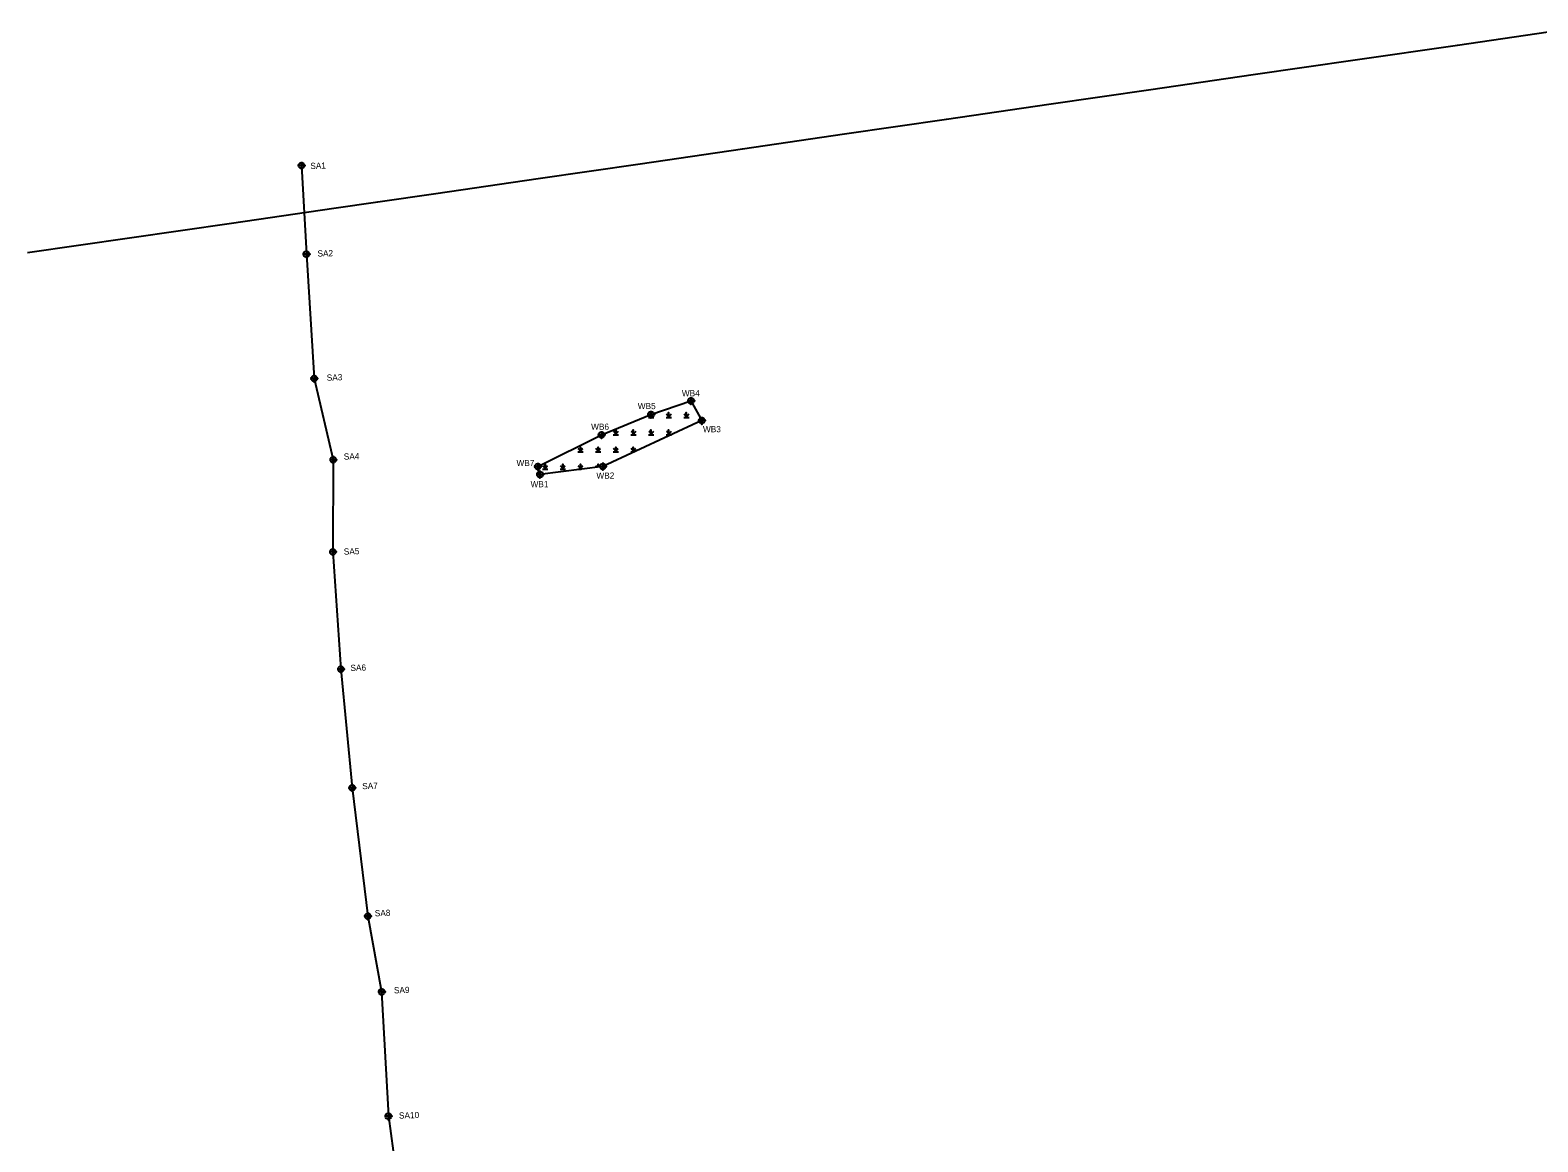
# Model space of a CAD drawing. Extents: x 1616941 to 1621864, y 896903 to 900301.
# Drawn here: x 1619402 to 1620623, y 899343 to 900243 of the extents above; entities that cross this region are included whole.
import ezdxf

# ---------------------------------------------------------------- set-up
doc = ezdxf.new("R2010")
doc.units = 0
for name, color, linetype in [('Default', 7, 'Continuous'), ('Exist Hydro Swamp or Marsh', 7, 'Continuous'), ('Sheet Block Revision CELL', 7, 'Continuous'), ('Sheet Layout Plan Border', 7, 'Continuous'), ('Sheet North Arrow Point CELL', 7, 'Continuous'), ('Sheet Plan CELL', 7, 'Continuous'), ('Sheet Plot Border Outside CELL', 7, 'Continuous'), ('Sheet Sticker Exception Certification CELL', 7, 'Continuous')]:
    doc.layers.add(name, color=color, linetype=linetype)

msp = doc.modelspace()

# ---------------------------------------------------------------- linework, layer by layer
at = {"layer": 'Default'}
msp.add_lwpolyline([(1619400.1, 900062.7), (1619482.8, 900074.7), (1619565.5, 900086.7), (1619648.2, 900098.7), (1619683.8, 900103.9), (1619730.9, 900110.7), (1619813.7, 900122.7), (1619896.4, 900134.7), (1619979.1, 900146.8), (1620061.8, 900158.8), (1620144.5, 900170.8), (1620227.3, 900182.8), (1620310, 900194.8), (1620392.7, 900206.8), (1620475.4, 900218.8), (1620558.1, 900230.8), (1620640.9, 900242.8)], dxfattribs=at)
at = {"layer": 'Exist Hydro Swamp or Marsh'}
for points in [[(1619903, 899929.3), (1619905.1, 899929.3), (1619905.1, 899931.6)], [(1619905.1, 899931.6), (1619905.1, 899929.3), (1619907.3, 899929.3)], [(1619917.3, 899929.3), (1619919.4, 899929.3), (1619919.4, 899933.2), (1619919.4, 899929.3), (1619921.6, 899929.3)], [(1619931.6, 899929.3), (1619933.7, 899929.3), (1619933.7, 899933.2), (1619933.7, 899929.3), (1619935.9, 899929.3)], [(1619874.4, 899915.3), (1619876.5, 899915.3), (1619876.5, 899919.3), (1619876.5, 899915.3), (1619878.7, 899915.3)], [(1619888.7, 899915.3), (1619890.8, 899915.3), (1619890.8, 899919.3), (1619890.8, 899915.3), (1619893, 899915.3)], [(1619903, 899915.3), (1619905.1, 899915.3), (1619905.1, 899919.3), (1619905.1, 899915.3), (1619907.3, 899915.3)], [(1619917.3, 899915.3), (1619919.4, 899915.3), (1619919.4, 899919.3), (1619919.4, 899915.3), (1619921.6, 899915.3)], [(1619845.8, 899901.4), (1619847.9, 899901.4), (1619847.9, 899905.3), (1619847.9, 899901.4), (1619850.1, 899901.4)], [(1619860.1, 899901.4), (1619862.2, 899901.4), (1619862.2, 899905.3), (1619862.2, 899901.4), (1619864.4, 899901.4)], [(1619874.4, 899901.4), (1619876.5, 899901.4), (1619876.5, 899905.3), (1619876.5, 899901.4), (1619878.7, 899901.4)], [(1619888.7, 899901.4), (1619890.8, 899901.4), (1619890.8, 899905.3), (1619890.8, 899901.4), (1619891.5, 899901.4)], [(1619817.2, 899887.5), (1619819.3, 899887.5), (1619819.3, 899891.4), (1619819.3, 899887.5), (1619821.5, 899887.5)], [(1619831.5, 899887.5), (1619833.6, 899887.5), (1619833.6, 899891.4), (1619833.6, 899887.5), (1619835.8, 899887.5)], [(1619845.8, 899887.5), (1619847.9, 899887.5), (1619847.9, 899891.4), (1619847.9, 899887.5), (1619848.6, 899887.5)], [(1619862.2, 899889.2), (1619862.2, 899891.4), (1619862.2, 899889.2)]]:
    msp.add_lwpolyline(points, dxfattribs=at)
for centre, radius, start, end in [((1619902.1, 899929.1), 3.07, 4.1403, 44.2712), ((1619909.7, 899927.8), 4.81, 122.1274, 161.6222), ((1619916.4, 899929.1), 3.07, 4.1403, 67.535), ((1619924, 899927.8), 4.81, 122.1274, 161.6222), ((1619930.7, 899929.1), 3.07, 4.1403, 67.535), ((1619938.3, 899927.8), 4.81, 122.1274, 161.6222), ((1619873.5, 899915.1), 3.07, 4.1403, 67.535), ((1619881.1, 899913.8), 4.81, 122.1274, 161.6222), ((1619887.8, 899915.1), 3.07, 4.1403, 67.535), ((1619895.4, 899913.8), 4.81, 122.1274, 161.6222), ((1619902.1, 899915.1), 3.07, 4.1403, 67.535), ((1619909.7, 899913.8), 4.81, 122.1274, 161.6222), ((1619916.4, 899915.1), 3.07, 4.1403, 67.535), ((1619924, 899913.8), 4.81, 122.1274, 161.6222), ((1619844.9, 899901.2), 3.07, 4.1403, 67.535), ((1619852.5, 899899.9), 4.81, 122.1274, 161.6222), ((1619859.2, 899901.2), 3.07, 4.1403, 67.535), ((1619866.8, 899899.9), 4.81, 122.1274, 161.6222), ((1619873.5, 899901.2), 3.07, 4.1403, 67.535), ((1619881.1, 899899.9), 4.81, 122.1274, 161.6222), ((1619887.8, 899901.2), 3.07, 4.1403, 67.535), ((1619895.4, 899899.9), 4.81, 122.1274, 161.6222), ((1619816.3, 899887.2), 3.07, 4.1403, 67.535), ((1619823.9, 899885.9), 4.81, 122.1274, 161.6222), ((1619830.6, 899887.2), 3.07, 4.1403, 67.535), ((1619838.2, 899885.9), 4.81, 122.1274, 161.6222), ((1619844.9, 899887.2), 3.07, 4.1403, 67.535), ((1619852.5, 899885.9), 4.81, 122.1274, 161.6222), ((1619859.2, 899887.2), 3.07, 37.9535, 67.535), ((1619866.8, 899885.9), 4.81, 122.1274, 134.6539)]:
    msp.add_arc(centre, radius, start, end, dxfattribs=at)
at = {"layer": 'Sheet Block Revision CELL'}
msp.add_lwpolyline([(1619813.5, 899889.6), (1619865, 899915.3), (1619905.1, 899931.6), (1619937.5, 899942.7), (1619946.3, 899926.7), (1619866.2, 899889.7), (1619815.2, 899883.2)], close=True, dxfattribs=at)
at = {"layer": 'Sheet North Arrow Point CELL'}
for points in [[(1619622, 900136.2), (1619622, 900130.2), (1619622, 900133.2), (1619625, 900133.2), (1619619, 900133.2)], [(1619626, 900064.5), (1619626, 900058.5), (1619626, 900061.5), (1619629, 900061.5), (1619623, 900061.5)], [(1619632.3, 899963.8), (1619632.3, 899957.8), (1619632.3, 899960.8), (1619635.3, 899960.8), (1619629.3, 899960.8)], [(1619647.8, 899898.1), (1619647.8, 899892.1), (1619647.8, 899895.1), (1619650.8, 899895.1), (1619644.8, 899895.1)], [(1619647.5, 899823.4), (1619647.5, 899817.4), (1619647.5, 899820.4), (1619650.5, 899820.4), (1619644.5, 899820.4)], [(1619654, 899728.5), (1619654, 899722.5), (1619654, 899725.5), (1619657, 899725.5), (1619651, 899725.5)], [(1619663.1, 899632.4), (1619663.1, 899626.4), (1619663.1, 899629.4), (1619666.1, 899629.4), (1619660.1, 899629.4)], [(1619675.7, 899528.5), (1619675.7, 899522.5), (1619675.7, 899525.5), (1619678.7, 899525.5), (1619672.7, 899525.5)], [(1619687, 899467.2), (1619687, 899461.2), (1619687, 899464.2), (1619690, 899464.2), (1619684, 899464.2)], [(1619692.4, 899366.5), (1619692.4, 899360.5), (1619692.4, 899363.5), (1619695.4, 899363.5), (1619689.4, 899363.5)]]:
    msp.add_lwpolyline(points, dxfattribs=at)
for centre in [(1619622, 900133.2), (1619626, 900061.5), (1619632.3, 899960.8), (1619647.8, 899895.1), (1619647.5, 899820.4), (1619654, 899725.5), (1619663.1, 899629.4), (1619675.7, 899525.5), (1619687, 899464.2), (1619692.4, 899363.5)]:
    msp.add_circle(centre, 2.34, dxfattribs=at)
at = {"layer": 'Sheet Plan CELL'}
for points in [[(1619937.5, 899945.7), (1619937.5, 899939.7), (1619937.5, 899942.7), (1619940.5, 899942.7), (1619934.5, 899942.7)], [(1619905.1, 899934.6), (1619905.1, 899928.6), (1619905.1, 899931.6), (1619908.1, 899931.6), (1619902.1, 899931.6)], [(1619946.3, 899929.7), (1619946.3, 899923.7), (1619946.3, 899926.7), (1619949.3, 899926.7), (1619943.3, 899926.7)], [(1619865, 899918.3), (1619865, 899912.3), (1619865, 899915.3), (1619868, 899915.3), (1619862, 899915.3)], [(1619813.5, 899892.6), (1619813.5, 899886.6), (1619813.5, 899889.6), (1619816.5, 899889.6), (1619810.5, 899889.6)], [(1619815.2, 899886.2), (1619815.2, 899880.2), (1619815.2, 899883.2), (1619818.2, 899883.2), (1619812.2, 899883.2)], [(1619866.2, 899892.7), (1619866.2, 899886.7), (1619866.2, 899889.7), (1619869.2, 899889.7), (1619863.2, 899889.7)]]:
    msp.add_lwpolyline(points, dxfattribs=at)
for centre in [(1619937.5, 899942.7), (1619905.1, 899931.6), (1619946.3, 899926.7), (1619865, 899915.3), (1619813.5, 899889.6), (1619815.2, 899883.2), (1619866.2, 899889.7)]:
    msp.add_circle(centre, 2.34, dxfattribs=at)
at = {"layer": 'Sheet Sticker Exception Certification CELL'}
msp.add_lwpolyline([(1619622, 900133.2), (1619626, 900061.5), (1619632.3, 899960.8), (1619647.8, 899895.1), (1619647.5, 899820.4), (1619654, 899725.5), (1619663.1, 899629.4), (1619675.7, 899525.5), (1619687, 899464.2), (1619692.4, 899363.5), (1619703.9, 899279.5), (1619727.2, 899191.7), (1619766.7, 899068.6), (1619808.3, 898919.3), (1619830.8, 898861.7), (1619848, 898808.3), (1619911.6, 898624.6), (1619941.1, 898421.9)], dxfattribs=at)

# ---------------------------------------------------------------- texts
at = {"layer": 'Sheet Layout Plan Border'}
for s, p in [('SA1', (1619629.3, 900130.4)), ('SA2', (1619635.1, 900059.5)), ('SA3', (1619642.6, 899959)), ('SA4', (1619656.4, 899895.1)), ('SA5', (1619656.4, 899818.2)), ('SA6', (1619661.8, 899724)), ('SA7', (1619671.3, 899628.3)), ('SA8', (1619681.5, 899525.4)), ('SA9', (1619697, 899463)), ('SA10', (1619701.1, 899361.6))]:
    msp.add_text(s, height=5, rotation=1.7576, dxfattribs=at).set_placement(p)
at = {"layer": 'Sheet Plot Border Outside CELL'}
for s, p in [('WB4', (1619930.1, 899946.4)), ('WB5', (1619894.4, 899936)), ('WB6', (1619856.6, 899919.3)), ('WB3', (1619947.2, 899917.3)), ('WB7', (1619796.2, 899889.9)), ('WB2', (1619860.9, 899879.7)), ('WB1', (1619807.6, 899872.8))]:
    msp.add_text(s, height=5, dxfattribs=at).set_placement(p)

doc.saveas('drawing.dxf')
